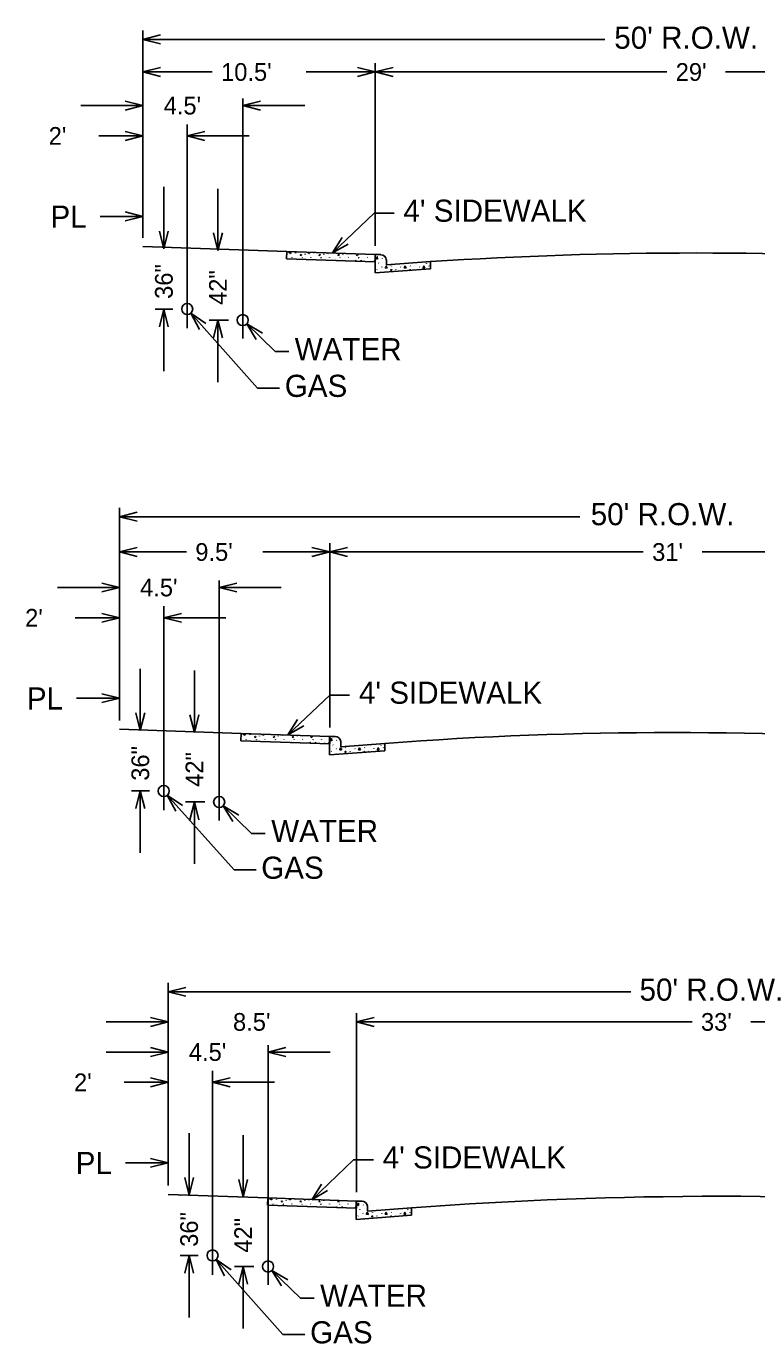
# Model space of a CAD drawing. Extents: x 524397 to 525117, y 3701341 to 3701821.
# Drawn here: x 524724.7 to 524790.7, y 3701587.8 to 3701706.9 of the extents above; entities that cross this region are included whole.
import ezdxf

# ---------------------------------------------------------------- set-up
doc = ezdxf.new("R2010")
doc.units = 0
doc.layers.add('Level 11', color=7, linetype='Continuous')

msp = doc.modelspace()

# ---------------------------------------------------------------- linework, layer by layer
at = {"layer": 'Level 11'}
for p, q in [((524735.24, 3701687.8), (524735.24, 3701706.53)), ((524735.24, 3701705.73), (524736.84, 3701706.13)), ((524776.97, 3701705.73), (524735.24, 3701705.73)), ((524736.84, 3701705.33), (524735.24, 3701705.73)), ((524735.24, 3701687.8), (524735.24, 3701703.58)), ((524735.24, 3701702.78), (524736.84, 3701703.18)), ((524741.5, 3701702.78), (524735.24, 3701702.78)), ((524736.84, 3701702.38), (524735.24, 3701702.78)), ((524749.99, 3701702.78), (524756.24, 3701702.78)), ((524754.64, 3701703.18), (524756.24, 3701702.78)), ((524756.24, 3701702.78), (524754.64, 3701702.38)), ((524756.24, 3701687.07), (524756.24, 3701703.58)), ((524756.24, 3701702.78), (524757.84, 3701703.18)), ((524782.59, 3701702.78), (524756.24, 3701702.78)), ((524757.84, 3701702.38), (524756.24, 3701702.78)), ((524787.9, 3701702.78), (524814.24, 3701702.78)), ((524744.26, 3701678.68), (524744.26, 3701700.37)), ((524729.64, 3701699.74), (524735.24, 3701699.74)), ((524733.64, 3701700.14), (524735.24, 3701699.74)), ((524735.24, 3701699.74), (524733.64, 3701699.34)), ((524744.26, 3701699.74), (524745.86, 3701700.14)), ((524749.87, 3701699.74), (524744.26, 3701699.74)), ((524745.86, 3701699.34), (524744.26, 3701699.74)), ((524739.24, 3701679.61), (524739.24, 3701698.04)), ((524731.24, 3701697), (524735.24, 3701697)), ((524733.64, 3701697.4), (524735.24, 3701697)), ((524735.24, 3701697), (524733.64, 3701696.6)), ((524739.24, 3701697), (524740.84, 3701697.4)), ((524744.85, 3701697), (524739.24, 3701697)), ((524740.84, 3701696.6), (524739.24, 3701697)), ((524737.13, 3701692.4), (524737.13, 3701686.8)), ((524742.02, 3701692.23), (524742.02, 3701686.63)), ((524735.24, 3701689.72), (524731.37, 3701689.72)), ((524733.64, 3701690.13), (524735.24, 3701689.72)), ((524735.24, 3701689.72), (524733.64, 3701689.32)), ((524752.36, 3701686.42), (524756.14, 3701690.03)), ((524756.14, 3701690.03), (524757.94, 3701690.03)), ((524737.13, 3701686.8), (524736.73, 3701688.4)), ((524737.53, 3701688.4), (524737.13, 3701686.8)), ((524742.02, 3701686.63), (524741.62, 3701688.23)), ((524742.42, 3701688.23), (524742.02, 3701686.63)), ((524753.24, 3701687.81), (524752.36, 3701686.42)), ((524752.36, 3701686.42), (524753.79, 3701687.23)), ((524735.24, 3701687), (524748.25, 3701686.55)), ((524748.25, 3701686.55), (524748.22, 3701685.89)), ((524748.22, 3701685.89), (524756.24, 3701685.61)), ((524756.24, 3701686.27), (524748.25, 3701686.55)), ((524748.71, 3701686), (524748.7, 3701686.03)), ((524749.04, 3701686.41), (524749.02, 3701686.45)), ((524749.64, 3701685.99), (524749.62, 3701685.97)), ((524749.65, 3701686), (524749.64, 3701685.98)), ((524749.89, 3701686.33), (524749.89, 3701686.29)), ((524750.41, 3701686), (524750.4, 3701686.03)), ((524750.74, 3701686.41), (524750.72, 3701686.45)), ((524751.34, 3701685.99), (524751.32, 3701685.97)), ((524751.35, 3701686), (524751.34, 3701685.98)), ((524751.59, 3701686.33), (524751.59, 3701686.29)), ((524752.11, 3701686), (524752.1, 3701686.03)), ((524753.04, 3701685.99), (524753.02, 3701685.97)), ((524753.05, 3701686), (524753.04, 3701685.98)), ((524753.3, 3701686.33), (524753.29, 3701686.29)), ((524753.82, 3701686), (524753.8, 3701686.03)), ((524754.74, 3701685.99), (524754.73, 3701685.97)), ((524754.75, 3701686), (524754.74, 3701685.98)), ((524755, 3701686.31), (524754.99, 3701686.29)), ((524755.52, 3701686), (524755.5, 3701686.03)), ((524756.24, 3701684.61), (524756.24, 3701686.27)), ((524756.24, 3701686.27), (524756.75, 3701686.27)), ((524756.24, 3701685.61), (524756.24, 3701686.27)), ((524756.75, 3701686.27), (524756.74, 3701686.27)), ((524756.88, 3701685.91), (524756.87, 3701685.94)), ((524753.26, 3701685.74), (524753.25, 3701685.77)), ((524754.09, 3701685.68), (524754.09, 3701685.69)), ((524754.96, 3701685.74), (524754.95, 3701685.77)), ((524755.81, 3701685.66), (524755.79, 3701685.69)), ((524761.24, 3701684.98), (524756.24, 3701684.61)), ((524756.4, 3701684.92), (524756.39, 3701684.9)), ((524756.56, 3701685.5), (524756.54, 3701685.53)), ((524756.84, 3701685.15), (524756.83, 3701685.18)), ((524757.24, 3701685.81), (524757.24, 3701685.34)), ((524757.24, 3701685.34), (524761.24, 3701685.65)), ((524757.7, 3701685.23), (524757.69, 3701685.27)), ((524758.1, 3701684.92), (524758.09, 3701684.9)), ((524758.55, 3701685.15), (524758.53, 3701685.18)), ((524759.18, 3701685.49), (524759.17, 3701685.47)), ((524759.19, 3701685.49), (524759.18, 3701685.48)), ((524759.41, 3701685.23), (524759.39, 3701685.27)), ((524759.8, 3701684.92), (524759.79, 3701684.9)), ((524759.96, 3701685.5), (524759.95, 3701685.53)), ((524760.25, 3701685.15), (524760.23, 3701685.18)), ((524760.88, 3701685.49), (524760.87, 3701685.47)), ((524760.9, 3701685.5), (524760.88, 3701685.48)), ((524761.11, 3701685.23), (524761.09, 3701685.27)), ((524761.24, 3701685.65), (524761.24, 3701684.98)), ((524737.94, 3701681.35), (524736.33, 3701681.35)), ((524736.73, 3701679.75), (524737.13, 3701681.35)), ((524737.13, 3701675.75), (524737.13, 3701681.35)), ((524737.13, 3701681.35), (524737.53, 3701679.75)), ((524740.34, 3701679.51), (524739.57, 3701680.97)), ((524739.57, 3701680.97), (524740.93, 3701680.04)), ((524739.57, 3701680.97), (524745.6, 3701674.21)), ((524742.96, 3701680.35), (524741.22, 3701680.35)), ((524741.62, 3701678.75), (524742.02, 3701680.35)), ((524742.02, 3701674.75), (524742.02, 3701680.35)), ((524742.02, 3701680.35), (524742.42, 3701678.75)), ((524745.48, 3701678.59), (524744.62, 3701680)), ((524744.62, 3701680), (524746.04, 3701679.17)), ((524744.62, 3701680), (524747.18, 3701677.5)), ((524747.18, 3701677.5), (524748.43, 3701677.5)), ((524745.6, 3701674.21), (524747.59, 3701674.21)), ((524733.12, 3701644.17), (524733.12, 3701663.38)), ((524733.12, 3701662.58), (524734.72, 3701662.98)), ((524774.72, 3701662.58), (524733.12, 3701662.58)), ((524734.72, 3701662.18), (524733.12, 3701662.58)), ((524733.12, 3701644.17), (524733.12, 3701660.19)), ((524733.12, 3701659.39), (524734.72, 3701659.79)), ((524750.51, 3701659.79), (524752.12, 3701659.39)), ((524752.12, 3701643.51), (524752.12, 3701660.19)), ((524752.12, 3701659.39), (524753.72, 3701659.79)), ((524739.17, 3701659.39), (524733.12, 3701659.39)), ((524734.72, 3701658.99), (524733.12, 3701659.39)), ((524746.06, 3701659.39), (524752.12, 3701659.39)), ((524752.12, 3701659.39), (524750.51, 3701658.99)), ((524780.46, 3701659.39), (524752.12, 3701659.39)), ((524753.72, 3701658.99), (524752.12, 3701659.39)), ((524785.77, 3701659.39), (524814.12, 3701659.39)), ((524727.51, 3701656.18), (524733.12, 3701656.18)), ((524731.51, 3701656.58), (524733.12, 3701656.18)), ((524733.12, 3701656.18), (524731.51, 3701655.78)), ((524742.13, 3701635.12), (524742.13, 3701656.81)), ((524742.13, 3701656.18), (524743.73, 3701656.58)), ((524747.74, 3701656.18), (524742.13, 3701656.18)), ((524743.73, 3701655.78), (524742.13, 3701656.18)), ((524731.51, 3701653.84), (524733.12, 3701653.44)), ((524737.12, 3701636.05), (524737.12, 3701654.48)), ((524737.12, 3701653.44), (524738.72, 3701653.84)), ((524729.11, 3701653.44), (524733.12, 3701653.44)), ((524733.12, 3701653.44), (524731.51, 3701653.04)), ((524742.72, 3701653.44), (524737.12, 3701653.44)), ((524738.72, 3701653.04), (524737.12, 3701653.44)), ((524735, 3701648.84), (524735, 3701643.24)), ((524739.89, 3701648.67), (524739.89, 3701643.07)), ((524733.12, 3701646.17), (524729.24, 3701646.17)), ((524731.51, 3701646.57), (524733.12, 3701646.17)), ((524733.12, 3701646.17), (524731.51, 3701645.77)), ((524748.34, 3701642.85), (524752.12, 3701646.46)), ((524752.12, 3701646.46), (524753.92, 3701646.46)), ((524735, 3701643.24), (524734.6, 3701644.84)), ((524735.4, 3701644.84), (524735, 3701643.24)), ((524739.89, 3701643.07), (524739.49, 3701644.67)), ((524740.29, 3701644.67), (524739.89, 3701643.07)), ((524749.22, 3701644.24), (524748.34, 3701642.85)), ((524733.12, 3701643.37), (524744.12, 3701642.99)), ((524748.34, 3701642.85), (524749.77, 3701643.66)), ((524744.12, 3701642.99), (524744.1, 3701642.33)), ((524744.1, 3701642.33), (524752.12, 3701642.05)), ((524752.12, 3701642.71), (524744.12, 3701642.99)), ((524744.58, 3701642.44), (524744.57, 3701642.48)), ((524744.91, 3701642.86), (524744.89, 3701642.89)), ((524745.51, 3701642.44), (524745.49, 3701642.41)), ((524745.52, 3701642.44), (524745.51, 3701642.42)), ((524745.76, 3701642.77), (524745.76, 3701642.73)), ((524746.29, 3701642.44), (524746.27, 3701642.48)), ((524746.61, 3701642.86), (524746.59, 3701642.89)), ((524747.21, 3701642.44), (524747.19, 3701642.41)), ((524747.22, 3701642.44), (524747.21, 3701642.42)), ((524747.47, 3701642.77), (524747.46, 3701642.73)), ((524747.99, 3701642.44), (524747.97, 3701642.48)), ((524748.91, 3701642.44), (524748.9, 3701642.41)), ((524748.92, 3701642.44), (524748.91, 3701642.42)), ((524749.13, 3701642.18), (524749.12, 3701642.21)), ((524749.17, 3701642.77), (524749.16, 3701642.73)), ((524749.69, 3701642.44), (524749.67, 3701642.48)), ((524749.96, 3701642.12), (524749.96, 3701642.13)), ((524750.61, 3701642.44), (524750.6, 3701642.41)), ((524750.63, 3701642.44), (524750.61, 3701642.42)), ((524750.84, 3701642.18), (524750.82, 3701642.21)), ((524750.87, 3701642.75), (524750.87, 3701642.73)), ((524751.39, 3701642.44), (524751.38, 3701642.48)), ((524751.68, 3701642.1), (524751.66, 3701642.13)), ((524752.11, 3701641.05), (524752.11, 3701642.71)), ((524752.11, 3701642.71), (524752.62, 3701642.71)), ((524752.12, 3701642.05), (524752.12, 3701642.71)), ((524752.43, 3701641.94), (524752.41, 3701641.97)), ((524752.62, 3701642.71), (524752.61, 3701642.71)), ((524752.75, 3701642.35), (524752.74, 3701642.38)), ((524753.11, 3701642.25), (524753.11, 3701641.79)), ((524753.11, 3701641.79), (524757.11, 3701642.09)), ((524755.05, 3701641.93), (524755.04, 3701641.91)), ((524755.06, 3701641.93), (524755.05, 3701641.92)), ((524755.83, 3701641.94), (524755.82, 3701641.97)), ((524756.76, 3701641.93), (524756.74, 3701641.91)), ((524756.77, 3701641.94), (524756.76, 3701641.92)), ((524757.11, 3701642.09), (524757.11, 3701641.43)), ((524757.11, 3701641.43), (524752.11, 3701641.05)), ((524752.27, 3701641.37), (524752.26, 3701641.35)), ((524752.72, 3701641.59), (524752.7, 3701641.63)), ((524753.58, 3701641.68), (524753.56, 3701641.71)), ((524753.97, 3701641.37), (524753.96, 3701641.35)), ((524754.42, 3701641.59), (524754.4, 3701641.63)), ((524755.28, 3701641.68), (524755.26, 3701641.71)), ((524755.68, 3701641.37), (524755.66, 3701641.35)), ((524756.12, 3701641.59), (524756.11, 3701641.63)), ((524756.98, 3701641.68), (524756.96, 3701641.71)), ((524735.82, 3701637.79), (524734.2, 3701637.79)), ((524734.6, 3701636.19), (524735, 3701637.79)), ((524735, 3701632.19), (524735, 3701637.79)), ((524735, 3701637.79), (524735.4, 3701636.19)), ((524738.21, 3701635.95), (524737.44, 3701637.41)), ((524737.44, 3701637.41), (524738.8, 3701636.48)), ((524737.44, 3701637.41), (524743.47, 3701630.66)), ((524740.83, 3701636.79), (524739.09, 3701636.79)), ((524739.49, 3701635.19), (524739.89, 3701636.79)), ((524739.89, 3701631.19), (524739.89, 3701636.79)), ((524739.89, 3701636.79), (524740.29, 3701635.19)), ((524743.36, 3701635.03), (524742.49, 3701636.44)), ((524742.49, 3701636.44), (524743.91, 3701635.61)), ((524742.49, 3701636.44), (524745.05, 3701633.94)), ((524745.05, 3701633.94), (524746.3, 3701633.94)), ((524743.47, 3701630.66), (524745.46, 3701630.66)), ((524737.53, 3701602.11), (524737.53, 3701620.43)), ((524737.53, 3701619.63), (524739.13, 3701620.03)), ((524779.32, 3701619.63), (524737.53, 3701619.63)), ((524739.13, 3701619.23), (524737.53, 3701619.63)), ((524731.93, 3701616.91), (524737.53, 3701616.91)), ((524735.93, 3701617.31), (524737.53, 3701616.91)), ((524737.53, 3701616.91), (524735.93, 3701616.51)), ((524737.53, 3701602.11), (524737.53, 3701617.71)), ((524754.53, 3701601.52), (524754.53, 3701617.71)), ((524754.53, 3701616.91), (524756.13, 3701617.31)), ((524754.53, 3701616.91), (524756.13, 3701617.31)), ((524760.13, 3701616.91), (524754.53, 3701616.91)), ((524784.87, 3701616.91), (524754.53, 3701616.91)), ((524756.13, 3701616.51), (524754.53, 3701616.91)), ((524756.13, 3701616.51), (524754.53, 3701616.91)), ((524790.18, 3701616.91), (524820.52, 3701616.91)), ((524735.93, 3701614.59), (524737.53, 3701614.19)), ((524746.55, 3701593.13), (524746.55, 3701614.82)), ((524746.55, 3701614.19), (524748.15, 3701614.59)), ((524731.93, 3701614.19), (524737.53, 3701614.19)), ((524737.53, 3701614.19), (524735.93, 3701613.79)), ((524752.15, 3701614.19), (524746.55, 3701614.19)), ((524748.15, 3701613.79), (524746.55, 3701614.19)), ((524741.53, 3701594.05), (524741.53, 3701612.49)), ((524733.53, 3701611.45), (524737.53, 3701611.45)), ((524735.93, 3701611.85), (524737.53, 3701611.45)), ((524737.53, 3701611.45), (524735.93, 3701611.05)), ((524741.53, 3701611.45), (524743.13, 3701611.85)), ((524747.13, 3701611.45), (524741.53, 3701611.45)), ((524743.13, 3701611.05), (524741.53, 3701611.45)), ((524739.41, 3701606.85), (524739.41, 3701601.24)), ((524744.3, 3701606.68), (524744.3, 3701601.07)), ((524737.53, 3701604.17), (524733.65, 3701604.17)), ((524735.93, 3701604.57), (524737.53, 3701604.17)), ((524737.53, 3701604.17), (524735.93, 3701603.77)), ((524750.49, 3701600.84), (524754.27, 3701604.45)), ((524754.27, 3701604.45), (524756.08, 3701604.45)), ((524739.41, 3701601.24), (524739.01, 3701602.84)), ((524739.81, 3701602.84), (524739.41, 3701601.24)), ((524744.3, 3701601.07), (524743.9, 3701602.68)), ((524744.7, 3701602.68), (524744.3, 3701601.07)), ((524751.37, 3701602.24), (524750.49, 3701600.84)), ((524750.49, 3701600.84), (524751.93, 3701601.66)), ((524737.53, 3701601.31), (524746.53, 3701601)), ((524738.64, 3701601.24), (524738.61, 3701601.24)), ((524746.53, 3701601), (524746.51, 3701600.34)), ((524746.51, 3701600.34), (524754.53, 3701600.06)), ((524754.53, 3701600.72), (524746.53, 3701601)), ((524747, 3701600.45), (524746.98, 3701600.48)), ((524747.32, 3701600.86), (524747.31, 3701600.9)), ((524747.92, 3701600.44), (524747.91, 3701600.42)), ((524747.94, 3701600.45), (524747.92, 3701600.43)), ((524748.18, 3701600.77), (524748.18, 3701600.74)), ((524748.7, 3701600.45), (524748.69, 3701600.48)), ((524749.02, 3701600.86), (524749.01, 3701600.9)), ((524749.08, 3701600.94), (524749.1, 3701600.94)), ((524749.62, 3701600.44), (524749.61, 3701600.42)), ((524749.64, 3701600.45), (524749.62, 3701600.43)), ((524749.88, 3701600.77), (524749.88, 3701600.74)), ((524750.4, 3701600.45), (524750.39, 3701600.48)), ((524751.33, 3701600.44), (524751.31, 3701600.42)), ((524751.34, 3701600.45), (524751.33, 3701600.43)), ((524751.55, 3701600.19), (524751.53, 3701600.22)), ((524751.58, 3701600.77), (524751.58, 3701600.74)), ((524752.1, 3701600.45), (524752.09, 3701600.48)), ((524752.38, 3701600.13), (524752.38, 3701600.14)), ((524753.03, 3701600.44), (524753.01, 3701600.42)), ((524753.04, 3701600.45), (524753.03, 3701600.43)), ((524753.25, 3701600.19), (524753.24, 3701600.22)), ((524753.28, 3701600.76), (524753.28, 3701600.74)), ((524753.8, 3701600.45), (524753.79, 3701600.48)), ((524754.09, 3701600.11), (524754.08, 3701600.14)), ((524754.52, 3701599.06), (524754.52, 3701600.72)), ((524754.52, 3701600.72), (524755.04, 3701600.72)), ((524754.53, 3701600.06), (524754.53, 3701600.72)), ((524755.04, 3701600.72), (524755.02, 3701600.72)), ((524755.17, 3701600.36), (524755.15, 3701600.39)), ((524755.52, 3701600.25), (524755.52, 3701599.79)), ((524759.52, 3701599.43), (524754.52, 3701599.06)), ((524754.69, 3701599.37), (524754.67, 3701599.35)), ((524754.84, 3701599.95), (524754.83, 3701599.98)), ((524755.13, 3701599.6), (524755.12, 3701599.63)), ((524755.52, 3701599.79), (524759.52, 3701600.09)), ((524755.99, 3701599.68), (524755.98, 3701599.71)), ((524756.39, 3701599.37), (524756.37, 3701599.35)), ((524756.83, 3701599.6), (524756.82, 3701599.63)), ((524757.47, 3701599.94), (524757.45, 3701599.92)), ((524757.48, 3701599.94), (524757.47, 3701599.92)), ((524757.69, 3701599.68), (524757.68, 3701599.71)), ((524758.09, 3701599.37), (524758.08, 3701599.35)), ((524758.25, 3701599.95), (524758.23, 3701599.98)), ((524758.53, 3701599.6), (524758.52, 3701599.63)), ((524759.17, 3701599.94), (524759.16, 3701599.92)), ((524759.18, 3701599.95), (524759.17, 3701599.92)), ((524759.39, 3701599.68), (524759.38, 3701599.71)), ((524759.52, 3701600.09), (524759.52, 3701599.43)), ((524740.23, 3701595.8), (524738.61, 3701595.8)), ((524739.01, 3701594.2), (524739.41, 3701595.8)), ((524739.41, 3701590.2), (524739.41, 3701595.8)), ((524739.41, 3701595.8), (524739.81, 3701594.2)), ((524742.62, 3701593.96), (524741.85, 3701595.42)), ((524741.85, 3701595.42), (524743.22, 3701594.49)), ((524741.85, 3701595.42), (524747.89, 3701588.66)), ((524745.25, 3701594.8), (524743.5, 3701594.8)), ((524743.9, 3701593.2), (524744.3, 3701594.8)), ((524744.3, 3701589.2), (524744.3, 3701594.8)), ((524744.3, 3701594.8), (524744.7, 3701593.2)), ((524747.77, 3701593.04), (524746.9, 3701594.45)), ((524746.9, 3701594.45), (524748.33, 3701593.61)), ((524746.9, 3701594.45), (524749.47, 3701591.95)), ((524749.47, 3701591.95), (524750.71, 3701591.95)), ((524747.89, 3701588.66), (524749.87, 3701588.66))]:
    msp.add_line(p, q, dxfattribs=at)
for points in [[(524748.53, 3701686.54), (524748.45, 3701686.45), (524748.6, 3701686.38)], [(524748.6, 3701686.38), (524748.58, 3701686.54)], [(524749.57, 3701686.19), (524749.53, 3701686.28), (524749.45, 3701686.22), (524749.57, 3701686.19)], [(524750.18, 3701686.48), (524750.15, 3701686.45), (524750.3, 3701686.38)], [(524750.3, 3701686.38), (524750.29, 3701686.48)], [(524751.27, 3701686.19), (524751.23, 3701686.28), (524751.16, 3701686.22), (524751.27, 3701686.19)], [(524751.92, 3701686.42), (524752, 3701686.38)], [(524752.01, 3701686.38), (524752, 3701686.42)], [(524752.97, 3701686.19), (524752.93, 3701686.28), (524752.86, 3701686.22), (524752.97, 3701686.19)], [(524754.67, 3701686.19), (524754.63, 3701686.28), (524754.56, 3701686.22), (524754.67, 3701686.19)], [(524756.45, 3701685.87), (524756.42, 3701686.08), (524756.29, 3701685.94), (524756.44, 3701685.87)], [(524752.79, 3701685.73), (524752.79, 3701685.74), (524752.78, 3701685.73)], [(524754.53, 3701685.67), (524754.49, 3701685.74), (524754.46, 3701685.67)], [(524756.24, 3701685.64), (524756.19, 3701685.74), (524756.13, 3701685.61)], [(524757.32, 3701685.06), (524757.23, 3701685.24), (524757.15, 3701685.07), (524757.32, 3701685.06)], [(524757.73, 3701684.83), (524757.69, 3701684.92), (524757.62, 3701684.87), (524757.73, 3701684.83)], [(524759.03, 3701685.06), (524758.93, 3701685.24), (524758.85, 3701685.07), (524759.02, 3701685.06)], [(524759.42, 3701684.85), (524759.39, 3701684.92), (524759.32, 3701684.87), (524759.39, 3701684.84)], [(524760.73, 3701685.06), (524760.63, 3701685.24), (524760.56, 3701685.07), (524760.72, 3701685.06)], [(524756.91, 3701684.66), (524756.91, 3701684.67), (524756.89, 3701684.66)], [(524744.41, 3701642.98), (524744.32, 3701642.89), (524744.47, 3701642.82)], [(524744.48, 3701642.82), (524744.45, 3701642.98)], [(524745.44, 3701642.63), (524745.4, 3701642.72), (524745.33, 3701642.66), (524745.44, 3701642.63)], [(524746.05, 3701642.92), (524746.02, 3701642.89), (524746.17, 3701642.82)], [(524746.18, 3701642.82), (524746.16, 3701642.92)], [(524747.14, 3701642.63), (524747.1, 3701642.72), (524747.03, 3701642.66), (524747.14, 3701642.63)], [(524747.79, 3701642.86), (524747.87, 3701642.82)], [(524747.88, 3701642.82), (524747.87, 3701642.86)], [(524748.67, 3701642.17), (524748.66, 3701642.18), (524748.65, 3701642.17)], [(524748.84, 3701642.63), (524748.8, 3701642.72), (524748.73, 3701642.66), (524748.84, 3701642.63)], [(524750.4, 3701642.11), (524750.36, 3701642.18), (524750.33, 3701642.11)], [(524750.54, 3701642.63), (524750.5, 3701642.72), (524750.43, 3701642.66), (524750.54, 3701642.63)], [(524752.12, 3701642.08), (524752.06, 3701642.18), (524752, 3701642.05)], [(524752.32, 3701642.31), (524752.29, 3701642.52), (524752.16, 3701642.39), (524752.32, 3701642.32)], [(524752.78, 3701641.1), (524752.78, 3701641.11), (524752.76, 3701641.1)], [(524753.2, 3701641.5), (524753.1, 3701641.68), (524753.03, 3701641.51), (524753.19, 3701641.5)], [(524753.6, 3701641.27), (524753.56, 3701641.36), (524753.49, 3701641.31), (524753.6, 3701641.27)], [(524754.9, 3701641.5), (524754.8, 3701641.68), (524754.73, 3701641.51), (524754.89, 3701641.5)], [(524755.3, 3701641.29), (524755.26, 3701641.36), (524755.19, 3701641.31), (524755.26, 3701641.29)], [(524756.6, 3701641.5), (524756.5, 3701641.68), (524756.43, 3701641.51), (524756.6, 3701641.5)], [(524746.82, 3701600.99), (524746.73, 3701600.9), (524746.89, 3701600.83)], [(524746.89, 3701600.83), (524746.87, 3701600.98)], [(524747.85, 3701600.64), (524747.81, 3701600.72), (524747.74, 3701600.67), (524747.85, 3701600.64)], [(524748.47, 3701600.93), (524748.44, 3701600.9), (524748.59, 3701600.83)], [(524748.59, 3701600.83), (524748.58, 3701600.92)], [(524749.56, 3701600.64), (524749.51, 3701600.72), (524749.44, 3701600.67), (524749.56, 3701600.64)], [(524750.2, 3701600.87), (524750.29, 3701600.83)], [(524750.29, 3701600.83), (524750.29, 3701600.87)], [(524751.08, 3701600.18), (524751.07, 3701600.19), (524751.07, 3701600.18)], [(524751.26, 3701600.64), (524751.21, 3701600.72), (524751.14, 3701600.67), (524751.26, 3701600.64)], [(524752.81, 3701600.12), (524752.77, 3701600.19), (524752.74, 3701600.12)], [(524752.96, 3701600.64), (524752.92, 3701600.72), (524752.85, 3701600.67), (524752.96, 3701600.64)], [(524754.53, 3701600.09), (524754.48, 3701600.19), (524754.42, 3701600.06)], [(524754.73, 3701600.32), (524754.71, 3701600.52), (524754.58, 3701600.39), (524754.73, 3701600.32)], [(524755.2, 3701599.11), (524755.19, 3701599.12), (524755.18, 3701599.1)], [(524755.61, 3701599.5), (524755.51, 3701599.69), (524755.44, 3701599.52), (524755.61, 3701599.5)], [(524756.02, 3701599.28), (524755.97, 3701599.37), (524755.9, 3701599.32), (524756.02, 3701599.28)], [(524757.31, 3701599.5), (524757.22, 3701599.69), (524757.14, 3701599.52), (524757.31, 3701599.5)], [(524757.71, 3701599.3), (524757.67, 3701599.37), (524757.6, 3701599.32), (524757.68, 3701599.29)], [(524759.01, 3701599.5), (524758.92, 3701599.69), (524758.84, 3701599.52), (524759.01, 3701599.5)]]:
    msp.add_lwpolyline(points, dxfattribs=at)
for centre in [(524739.24, 3701681.35), (524744.26, 3701680.35), (524737.12, 3701637.79), (524742.13, 3701636.79), (524741.53, 3701595.8), (524746.55, 3701594.8)]:
    msp.add_circle(centre, 0.5, dxfattribs=at)
for centre, radius, start, end in [((524756.74, 3701685.77), 0.494, 3.7079, 90.7668), ((524785.24, 3701317.88), 368.54, 86.2653, 93.7347), ((524783.11, 3701297.66), 345.41, 85.6819, 94.3176), ((524752.62, 3701642.22), 0.494, 3.7079, 90.7668), ((524755.03, 3701600.22), 0.494, 3.7079, 90.7668), ((524787.52, 3701229.22), 371.93, 85.6817, 94.3176)]:
    msp.add_arc(centre, radius, start, end, dxfattribs=at)

# ---------------------------------------------------------------- texts
for s, height, p in [("50' R.O.W.", 2, (524777.84, 3701704.88)), ("10.5'", 1.601, (524742.3, 3701701.98)), ("29'", 1.601, (524783.39, 3701701.98)), ("4.5'", 1.601, (524737.11, 3701698.94)), ("2'", 1.601, (524726.72, 3701696.2)), ('PL', 2, (524726.88, 3701688.71)), ("4' SIDEWALK", 2, (524758.78, 3701689.24)), ('WATER', 2, (524748.96, 3701676.72)), ('GAS', 2, (524748.06, 3701673.41)), ("50' R.O.W.", 2, (524775.71, 3701661.81)), ("9.5'", 1.601, (524739.97, 3701658.59)), ("31'", 1.601, (524781.26, 3701658.59)), ("4.5'", 1.601, (524734.98, 3701655.38)), ("2'", 1.601, (524724.59, 3701652.64)), ('PL', 2, (524724.75, 3701645.15)), ("4' SIDEWALK", 2, (524754.76, 3701645.67)), ('WATER', 2, (524746.83, 3701633.17)), ('GAS', 2, (524745.93, 3701629.85)), ("50' R.O.W.", 2, (524780.12, 3701618.83)), ("8.5'", 1.601, (524743.38, 3701616.11)), ("33'", 1.601, (524785.67, 3701616.11)), ("4.5'", 1.601, (524739.39, 3701613.39)), ("2'", 1.601, (524729.01, 3701610.65)), ('PL', 2, (524729.16, 3701603.16)), ("4' SIDEWALK", 2, (524756.91, 3701603.66)), ('WATER', 2, (524751.25, 3701591.17)), ('GAS', 2, (524750.35, 3701587.85))]:
    msp.add_text(s, height=height, dxfattribs=at).set_placement(p)
for s, p in [('36"', (524737.93, 3701682.27)), ('42"', (524742.82, 3701681.72)), ('36"', (524735.8, 3701638.71)), ('42"', (524740.69, 3701638.16)), ('36"', (524740.21, 3701596.58)), ('42"', (524745.1, 3701596.05))]:
    msp.add_text(s, height=1.601, rotation=90, dxfattribs=at).set_placement(p)

doc.saveas('drawing.dxf')
